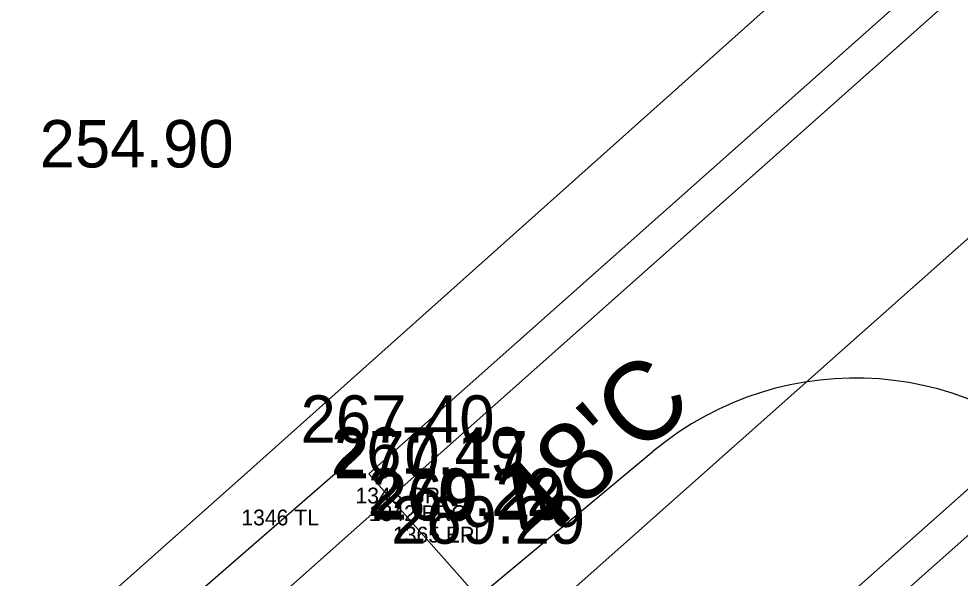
# Model space of a CAD drawing. Extents: x 49683 to 58852, y 49525 to 54803.
# Drawn here: x 53410.4 to 53470, y 51484.6 to 51520 of the extents above; entities that cross this region are included whole.
import ezdxf

# ---------------------------------------------------------------- set-up
doc = ezdxf.new("R2010")
doc.units = 0
for name, color, linetype in [('Level 1', 7, 'Continuous'), ('Level 11', 7, 'Continuous'), ('Level 18', 7, 'Continuous'), ('Level 3', 7, 'Continuous'), ('Level 32', 7, 'Continuous'), ('Level 48', 7, 'Continuous'), ('Level 5', 7, 'Continuous'), ('Level 53', 7, 'Continuous'), ('Level 55', 7, 'Continuous'), ('Level 57', 7, 'Continuous'), ('Level 61', 7, 'Continuous'), ('Level 7', 7, 'Continuous')]:
    doc.layers.add(name, color=color, linetype=linetype)

msp = doc.modelspace()

# ---------------------------------------------------------------- linework, layer by layer
at = {"layer": 'Level 1'}
msp.add_line((52544.807, 50683.302), (55534.583, 53340.862), dxfattribs=at)
at = {"layer": 'Level 11'}
for p, q in [((53424.495, 51490.929), (53894.91, 51911.927)), ((53157.705, 51254.454), (53424.495, 51490.929))]:
    msp.add_line(p, q, dxfattribs=at)
at = {"layer": 'Level 18'}
msp.add_line((53395.485, 51446.762), (53450.551, 51492.621), dxfattribs=at)
msp.add_arc((53463.35, 51477.253), 20, 41.63337, 129.78743, dxfattribs=at)
at = {"layer": 'Level 3'}
for p, q in [((53434.092, 51489.844), (53883.273, 51889.178)), ((53449.718, 51471.806), (53898.742, 51870.567)), ((53162.497, 51248.316), (53434.092, 51489.844))]:
    msp.add_line(p, q, dxfattribs=at)
at = {"layer": 'Level 5'}
for p, q in [((53432.563, 51491.203), (53881.993, 51890.68)), ((53900.074, 51869.402), (53451.19, 51470.163)), ((53451.19, 51470.163), (53432.563, 51491.203))]:
    msp.add_line(p, q, dxfattribs=at)
at = {"layer": 'Level 7'}
msp.add_line((53431.716, 51492.319), (53399.953, 51464.721), dxfattribs=at)

# ---------------------------------------------------------------- texts
at = {"layer": 'Level 32'}
for s, p in [('254.90', (53411.738, 51510.583)), ('267.40', (53428.244, 51493.16)), ('267.49', (53430.166, 51491.13)), ('270.17', (53430.349, 51490.907)), ('270.22', (53432.485, 51488.533)), ('269.29', (53432.76, 51488.284)), ('269.29', (53433.972, 51486.767))]:
    msp.add_text(s, height=3, dxfattribs=at).set_placement(p)
at = {"layer": 'Level 48'}
msp.add_text("48'C", height=5, rotation=41.63336, dxfattribs=at).set_placement((53443.152, 51486.459))
at = {"layer": 'Level 53'}
msp.add_text('1365 EPL', height=1, dxfattribs=at).set_placement((53434.092, 51486.844))
at = {"layer": 'Level 55'}
msp.add_text('1342 BRC', height=1, dxfattribs=at).set_placement((53432.563, 51488.203))
at = {"layer": 'Level 57'}
msp.add_text('1343 GRA', height=1, dxfattribs=at).set_placement((53431.716, 51489.319))
at = {"layer": 'Level 61'}
msp.add_text('1346 TL', height=1, dxfattribs=at).set_placement((53424.495, 51487.929))

doc.saveas('drawing.dxf')
